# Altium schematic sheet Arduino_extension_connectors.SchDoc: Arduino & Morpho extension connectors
size A4; Date: Not used; ApprovedBy: Not used; CheckedBy: Not used; Author: Not used; CompanyName: STMicroelectronics; DrawnBy: Not used; Engineer: Not used; Organization: Not used; Address1: Not used; Address2: Not used; Address3: Not used; Address4: Not used; DocumentNumber: 5; Revision: Not used; SheetNumber: 5; SheetTotal: 8
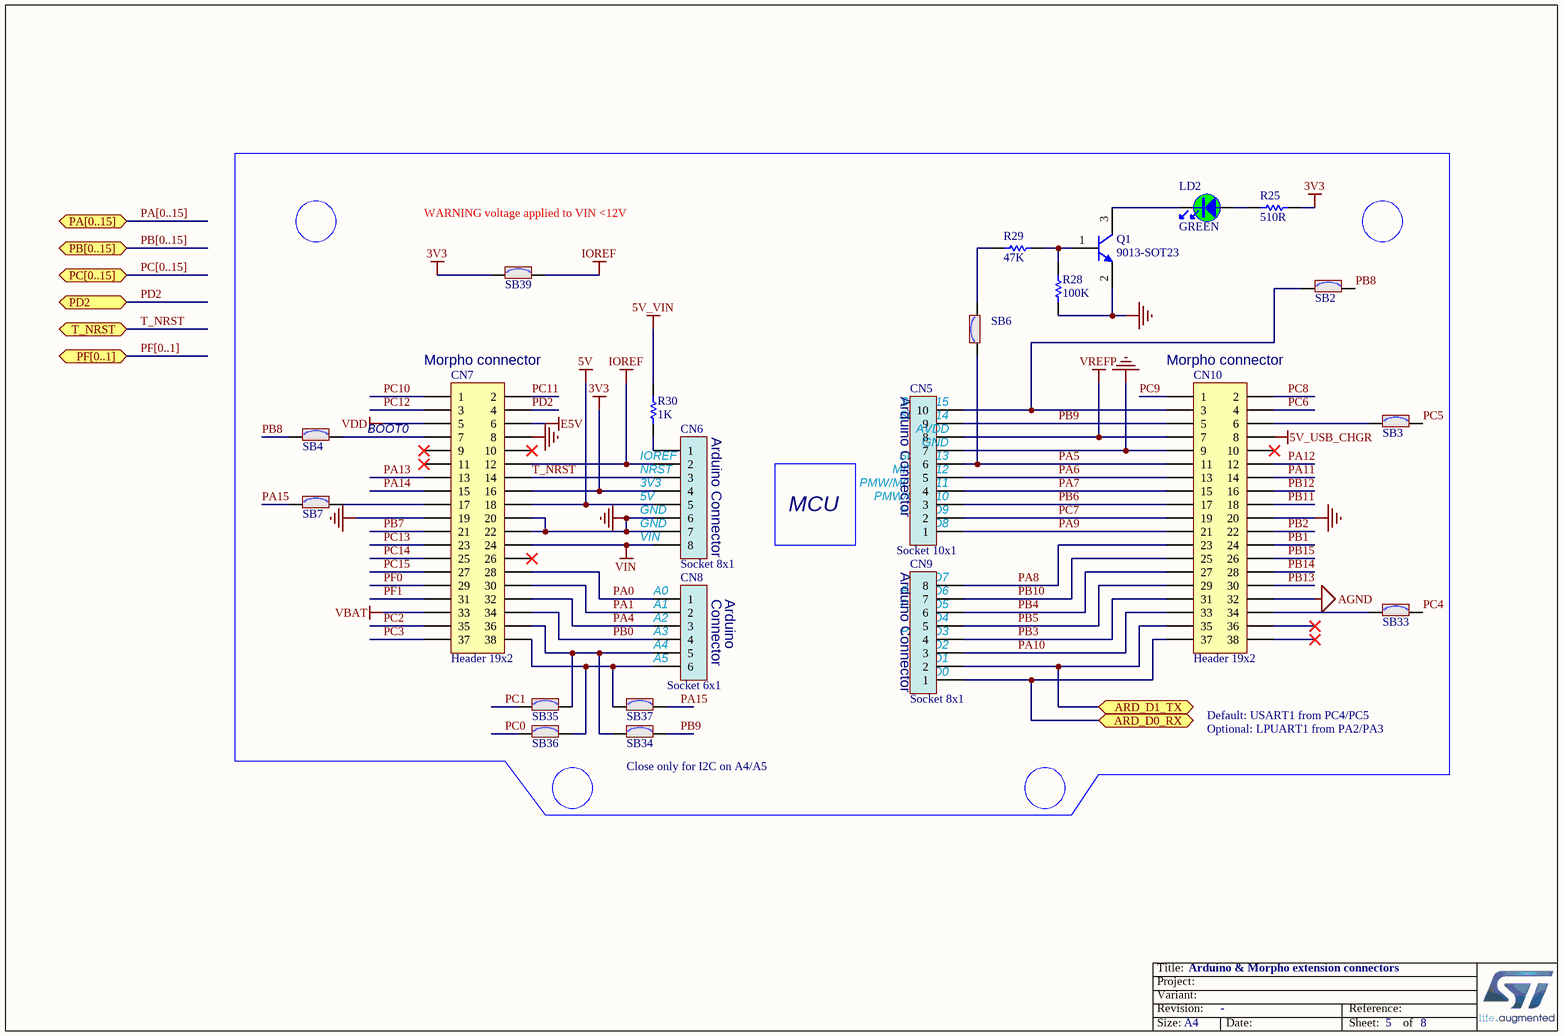
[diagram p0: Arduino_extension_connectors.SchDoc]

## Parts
CN5  value Socket 10x1  [CON_SAMTEC_SSW-110-03-X-S]
CN6  value Socket 8x1  [CON_SAMTEC_SSW-108-03-X-S]
CN7  value Header 19x2  [CON_SAMTEC_TSW-119-09-X-D]
CN8  value Socket 6x1  [CON_SAMTEC_SSW-106-03-X-S]
CN9  value Socket 8x1  [CON_SAMTEC_SSW-108-03-X-S]
CN10  value Header 19x2  [CON_SAMTEC_TSW-119-09-X-D]
LD2  value GREEN  [LED_0603_GREEN]
Q1  value 9013-SOT23  [NPN_SOT23]
R25  value 510R  [R0603]
R28  value 100K  [R0603]
R29  value 47K  [R0603]
R30  value 1K  [R0603]
SB2  (no value)  [SOLDER-BRIDGE_R0603-0R]
SB3  (no value)  [SOLDER-BRIDGE_R0603-0R]
SB4  (no value)  [SOLDER-BRIDGE_R0603-0R]
SB6  (no value)  [SOLDER-BRIDGE_R0603-0R]
SB7  (no value)  [SOLDER-BRIDGE_R0603-0R]
SB33  (no value)  [SOLDER-BRIDGE_R0603-0R]
SB34  (no value)  [SOLDER-BRIDGE_R0603-0R]
SB35  (no value)  [SOLDER-BRIDGE_R0603-0R]
SB36  (no value)  [SOLDER-BRIDGE_R0603-0R]
SB37  (no value)  [SOLDER-BRIDGE_R0603-0R]
SB39  (no value)  [SOLDER-BRIDGE_R0603-0R]

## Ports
ARD_D0_RX, ARD_D1_TX, PA[0..15] (bidir), PB[0..15] (bidir), PC[0..15] (bidir), PD2, PF[0..1] (bidir), T_NRST

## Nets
3V3: CN6.4 CN7.16 R25.1 SB39.1
5V: CN6.5 CN7.18
5V_USB_CHGR: CN10.8
5V_VIN: R30.2
AGND: CN10.32
E5V: CN7.6
GND: CN5.7 CN6.6 CN6.7 CN7.8 CN7.19 CN7.20 CN7.22 CN10.9 CN10.20 Q1.2(E) R28.1
IOREF: CN6.2 CN7.12 SB39.2
VBAT: CN7.33
VDD: CN7.5
VIN: CN6.8 CN7.24
VREFP: CN5.8 CN10.7
ARD_D0_RX: CN9.1 CN10.37 ; port ARD_D0_RX
ARD_D1_TX: CN9.2 CN10.35 ; port ARD_D1_TX
PA0: CN7.28 CN8.1
PA1: CN7.30 CN8.2
PA4: CN7.32 CN8.3
PA5: CN5.6 CN10.11 SB6.1
PA6: CN5.5 CN10.13
PA7: CN5.4 CN10.15
PA8: CN9.8 CN10.23
PA9: CN5.1 CN10.21
PA10: CN9.3 CN10.33
PA11: CN10.14
PA12: CN10.12
PA13: CN7.13
PA14: CN7.15
PA15: SB7.1 SB37.2
PB0: CN7.34 CN8.4
PB1: CN10.24
PB2: CN10.22
PB3: CN9.4 CN10.31
PB4: CN9.6 CN10.27
PB5: CN9.5 CN10.29
PB6: CN5.3 CN10.17
PB7: CN7.21
PB8: SB2.2 SB4.1
PB9: CN5.9 CN10.5 SB34.2
PB10: CN9.7 CN10.25
PB11: CN10.18
PB12: CN10.16
PB13: CN10.30
PB14: CN10.28
PB15: CN10.26
PC0: SB36.1
PC1: SB35.1
PC2: CN7.35
PC3: CN7.37
PC4: SB33.2
PC5: SB3.2
PC6: CN10.4
PC7: CN5.2 CN10.19
PC8: CN10.2
PC9: CN10.1
PC10: CN7.1
PC11: CN7.2
PC12: CN7.3
PC13: CN7.23
PC14: CN7.25
PC15: CN7.27
PD2: CN7.4 ; port PD2
PF0: CN7.29
PF1: CN7.31
T_NRST: CN6.3 CN7.14 ; port T_NRST
NetCN5_10: CN5.10 CN10.3 SB2.1
NetCN6_1: CN6.1 R30.1
NetCN7_7: CN7.7 SB4.2
NetCN7_17: CN7.17 SB7.2
NetCN7_36: CN7.36 CN8.5 SB34.1 SB35.2
NetCN7_38: CN7.38 CN8.6 SB36.2 SB37.1
NetCN10_6: CN10.6 SB3.1
NetCN10_34: CN10.34 SB33.1
NetLD2_1: LD2.1 R25.2
NetLD2_2: LD2.2 Q1.3(C)
NetQ1_1: Q1.1(B) R28.2 R29.2
NetR29_1: R29.1 SB6.2

Not connected (* = marked no-connect by the designer): CN7 9* 10* 11* 26*; CN10 10* 36* 38*

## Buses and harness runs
bus PA[0..15] = port PA[0..15]
bus PB[0..15] = port PB[0..15]
bus PC[0..15] = port PC[0..15]
bus PF[0..1] = port PF[0..1]

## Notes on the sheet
- WARNING voltage applied to VIN <12V
- (near CN7) Morpho connector
- (near CN10) Morpho connector
- (near CN7) BOOT0
- (near CN6) Arduino Connector
- (near CN5) Arduino Connector
- (near CN5) SDA/D14
- (near CN5) SCL/D15
- (near CN5) AVDD
- (near CN5) GND
- (near CN6) GND
- (near CN6) 5V
- (near CN6) 3V3
- (near CN6) NRST
- (near CN6) IOREF
- MCU
- (near CN5) PMW/D9
- (near CN5) PMW/CS/D10
- (near CN5) SCK/D13
- (near CN5) MISO/D12
- (near CN5) PMW/MOSI/D11
- (near CN6) VIN
- (near CN9) Arduino Connector
- (near CN9) D7
- (near CN5) D8
- (near CN8) A0
- (near CN8) A1
- (near CN8) A2
- (near CN8) A3
- (near CN8) A4
- (near CN8) Connector
- (near CN8) Arduino
- (near CN9) D2
- (near CN9) D4
- (near CN9) PMW/D3
- (near CN9) PMW/D5
- (near CN9) PMW/D6
- (near CN8) A5
- (near CN9) RX/D0
- (near CN9) TX/D1
- (near SB34) Close only for I2C on A4/A5
- Default: USART1 from PC4/PC5
  Optional: LPUART1 from PA2/PA3

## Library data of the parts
CN5 = MCD-00262: Socket, 10x1, 2.54mm, VR, TH, Height 8.51mm/10mm; Manufacturer_Part_Number: SSW-110-03-x-S; Manufacturer: SAMTEC; Part_Type: Connector; Provided_By: Subcon; Initial_Board_Reference: MB1319
CN6 CN9 = MCD-00261: Socket, 8x1, 2.54mm, VR, TH, Height 8.51mm/10mm; Manufacturer_Part_Number: SSW-108-03-x-S; Manufacturer: SAMTEC; Part_Type: Connector; Provided_By: Subcon; Initial_Board_Reference: MB1319
CN7 CN10 = MCD-00213: Header, 19x2, 2,54mm, VR, TH, Height 5.84mm/10.16mm; Manufacturer_Part_Number: TSW-119-09-x-D; Manufacturer: SAMTEC; Part_Type: Connector; Provided_By: Subcon; Initial_Board_Reference: MB1319
CN8 = MCD-00260: Socket, 6x1, 2.54mm, VR, TH, Height 8.51mm/10mm; Manufacturer_Part_Number: SSW-106-03-x-S; Manufacturer: SAMTEC; Part_Type: Connector; Provided_By: Subcon; Initial_Board_Reference: MB1319
LD2 = MCD-00050: LED, Green, 0603; Manufacturer_Part_Number: 19-213SYGC/S530-E2/TR8; Manufacturer: EVERLIGHT; Part_Type: Display; ECCN_US: EAR99; ECCN_EU: NEC; Provided_By: Subcon; Initial_Board_Reference: MB1274
Q1 = MCD-00073: NPN Bipolar Transistor; Part_Type: IC; Manufacturer_Part_Number: BSR14; Manufacturer: NXP; ECCN_US: EAR99; ECCN_EU: NEC; Provided_By: Subcon; Initial_Board_Reference: MB1274
R25 = MCD-00225: Resistor,510R,0603,1%,1/10W; Manufacturer_Part_Number: RC0603FR-07510RL; Manufacturer: YAGEO; Provided_By: Subcon; Initial_Board_Reference: MB1319
R28 = MCD-00223: Resistor,100K,0603,1%,1/10W; Manufacturer_Part_Number: RC0603FR-07100KL; Manufacturer: YAGEO; Provided_By: Subcon; Initial_Board_Reference: MB1319
R29 = MCD-00222: Resistor,47K,0603,1%,1/10W; Manufacturer_Part_Number: RC0603FR-0747KL; Manufacturer: YAGEO; Provided_By: Subcon; Initial_Board_Reference: MB1319
R30 = MCD-00070: Resistor,1K,0603,1%,1/10W; Manufacturer_Part_Number: RC0603FR-071KL; Manufacturer: YAGEO; Provided_By: Subcon; Initial_Board_Reference: MB1274
SB2-SB4 SB6 SB7 SB33-SB37 SB39 = MCD-00071: Solder Bridge ON; Part_Type: Mechanical; Provided_By: Subcon; Initial_Board_Reference: MB1274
